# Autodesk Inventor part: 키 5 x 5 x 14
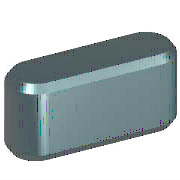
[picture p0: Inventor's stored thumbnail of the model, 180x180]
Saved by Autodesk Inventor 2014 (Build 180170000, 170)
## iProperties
IsCustomPart: 1
Created: 2012-02
Part Number: 키 5 x 5 x 14
Material: 강철, 연강
Description: 키 및 해당 키홈
Document SubType Name: Modeling
Standard: KS B 1311
Designer: mduedu
Standards Organization: KS
Language: ko-KR
Size Designation: 5 x 5 x 14
Categories: <MemberInstance><Categories><Category DisplayName="샤프트 부품" InternalName="7f7aeb1f-a693-4053-b835-cee3144e0d98" Mnemonic="SHFT"><Category DisplayName="키" Interna
Density: 1 g/cm^3
Appearance: Yellow
Author: mduedu
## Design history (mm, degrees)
sketch "스케치1"
  geometry: L1 (2.5, 2.5)-(11.5, 2.5); L2 (11.5, -2.5)-(2.5, -2.5); L3 (0, 9.4)-(0, -7.4) reference; L4 (-5, 0)-(30, 0) reference; L5 (14, 0)-(14, 7); A1 r 2.5 centre (2.5, 0) between (2.5, 2.5) and (2.5, -2.5); A2 r 2.5 centre (11.5, 0) between (11.5, -2.5) and (11.5, 2.5)
  constraints: 6 end point, 5 point on circle, 4 tangent, 3 point on line, 2 centre point, 1 horizontal, 1 parallel, 1 perpendicular
  dimensions: "d0" = 2.5 radius of A1 (= 0.5 x PB); "d13" = 2.5 radius of A2 (= 0.5 x PB); "d14" = 14 distance between parallel lines of L5 L3 (= NLG)
extrude "본체1" new body sketch "스케치1" taper "d3" = 0 deg; stored distance "d4" = 10
workplane "Work Plane3"
body "Solid1"
workplane "Work Plane1"
workplane "Work Plane2"
chamfer "모따기1" distance "d8" = 0.4 (= PHH); stored, may be unused: second distance "d9" = 0.4 (= PHH), angle "d15" = 45 deg
other parameters: "d1" = -3 (= -PNT), "d2" = 2 (= PH - PNT), "NLG" = 14 [user parameter; used in 3 equation terms], "PB" = 5 [user parameter; used in 2 equation terms], "PNT" = 3 [user parameter; used in 2 equation terms], "PH" = 5 [user parameter; used in 1 equation term], "PHH" = 0.4 [user parameter; used in 2 equation terms], "d10" = 0, "d16" = 0, "d17" = 0, "d18" = 0, "WDMIN" = 12 [user parameter], "PLB2" = 14 (= NLG) [user parameter], "WDMAX" = 17 [user parameter], "PLB1" = 14 (= NLG) [user parameter], "RR" = 0.16 [user parameter], "PUEB" = 2.3 [user parameter]
